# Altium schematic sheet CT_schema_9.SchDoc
size 308 x 195 mm
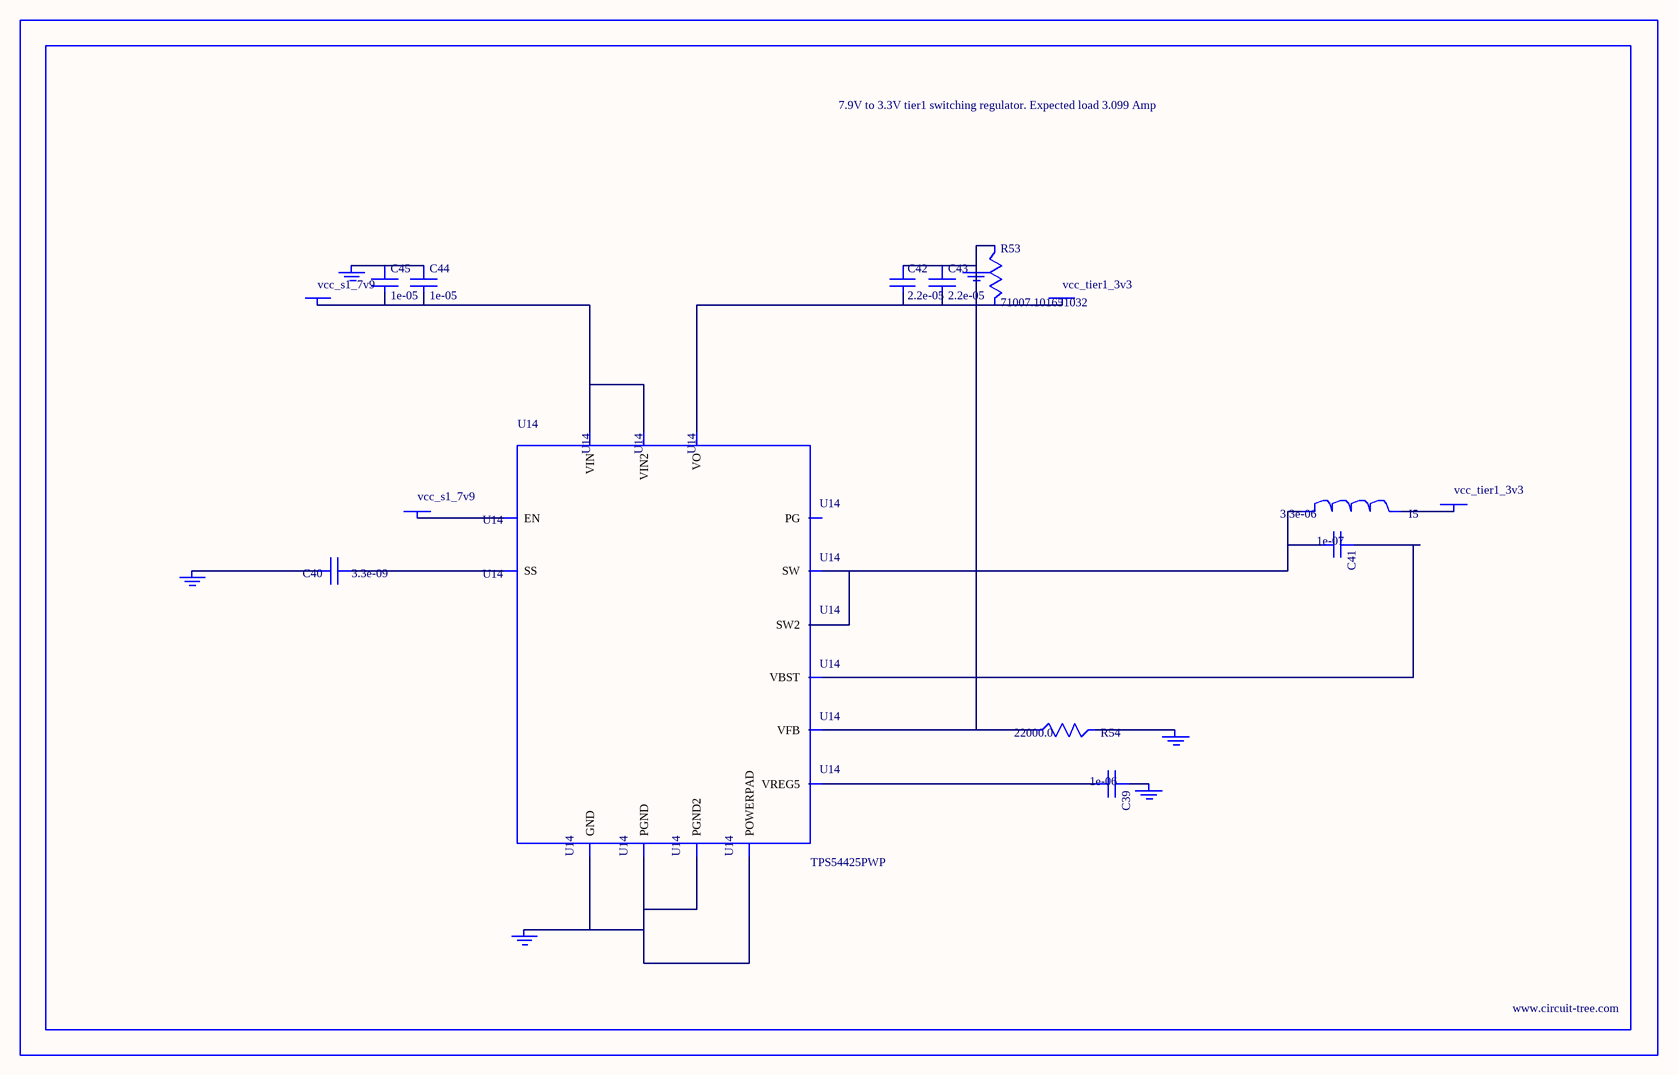
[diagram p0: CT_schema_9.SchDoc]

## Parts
BORDER8  (no value)
C39  1e-06  [C0603]
C40  3.3e-09  [C0402]
C41  1e-07  [C0402]
C42  2.2e-05  [C1210]
C43  2.2e-05  [C1210]
C44  1e-05  [C1206]
C45  1e-05  [C1206]
GND_INSTANCE_8_0  (no value)
GND_INSTANCE_8_1  (no value)
GND_INSTANCE_8_2  (no value)
GND_INSTANCE_8_3  (no value)
GND_INSTANCE_8_4  (no value)
GND_INSTANCE_8_5  (no value)
I5  3.3e-06  [WE-HCI_7030/7040/7050]
POWER_INSTANCE_8_0  vcc_tier1_3v3
POWER_INSTANCE_8_1  vcc_s1_7v9
POWER_INSTANCE_8_2  vcc_tier1_3v3
POWER_INSTANCE_8_3  vcc_s1_7v9
R53  71007.101651032  [R0603]
R54  22000.0  [R0603]
U14  TPS54425PWP  [HTSSOP14]

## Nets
NetC39_1: C39.1 GND_INSTANCE_8_2.0(GND)
NetC39_2: C39.2 U14.3(VREG5)
NetC40_1: C40.1 U14.4(SS)
NetC40_2: C40.2 GND_INSTANCE_8_3.0(GND)
NetC41_1: C41.1 U14.12(VBST)
NetC41_2: C41.2 I5.1 U14.10(SW) U14.11(SW2)
NetC42_1: C42.1 C43.1 GND_INSTANCE_8_0.0(GND) R53.1 R54.1 U14.2(VFB)
NetC42_2: C42.2 C43.2 POWER_INSTANCE_8_0.0(PWR) R53.2 U14.1(VO)
NetC44_1: C44.1 C45.1 GND_INSTANCE_8_5.0(GND)
NetC44_2: C44.2 C45.2 POWER_INSTANCE_8_3.0(PWR) U14.13(VIN) U14.14(VIN2)
NetGND_INSTANCE_8_1_0: GND_INSTANCE_8_1.0(GND) R54.2
NetGND_INSTANCE_8_4_0: GND_INSTANCE_8_4.0(GND) U14.5(GND) U14.8(PGND) U14.9(PGND2) U14.15(POWERPAD)
NetI5_2: I5.2 POWER_INSTANCE_8_2.0(PWR)
NetPOWER_INSTANCE_8_1_0: POWER_INSTANCE_8_1.0(PWR) U14.7(EN)

Not connected (* = marked no-connect by the designer): U14 6(PG)

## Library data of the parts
BORDER8 = BORDER_PAGE8
C39 = C0603C105K3RACTU
C40 = C0402C332K3RAC
C41 = C0402C104K3RACTU
C42 C43 = GRM32ER61E226ME15L
C44 C45 = C1206C106K3RACTU
GND_INSTANCE_8_0-GND_INSTANCE_8_5 = GND
I5 = 744314330
POWER_INSTANCE_8_0-POWER_INSTANCE_8_3 = PWR
R53 = R53
R54 = RC0603JR-0722KL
